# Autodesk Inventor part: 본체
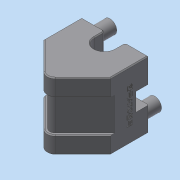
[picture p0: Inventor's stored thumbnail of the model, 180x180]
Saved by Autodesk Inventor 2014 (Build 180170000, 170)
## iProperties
Created: 2025-02
Part Number: 본체
Material: 일반
Document SubType Name: Modeling
Designer: dg
Density: 1 g/cm^3
Appearance: 기본값
Author: dg
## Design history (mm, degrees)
sketch "스케치1"
  geometry: L1 (-37, -21)-(0, -58); L2 (0, -58)-(37, -21); L3 (-37, -21)-(-37, 21); L4 (-37, 21)-(37, 21); L5 (37, 21)-(37, -21); 3 further points
  constraints: 10 end point, 2 horizontal alignment, 2 midpoint, 2 vertical alignment, 1 parallel, 1 perpendicular, 1 vertical
  dimensions: "d1" = 90 deg angle of L2 L1; "d2" = 42 distance of L4.end L2.end; "d3" = 74 distance of L3.end L4.end
extrude "돌출1" new body sketch "스케치1" stored distance "d4" = 74; taper "d5" = 0 deg
sketch "스케치2"
  geometry: L1 (37, 21)-(-37, 21) reference; L2 (-37, 21)-(-37, -21) reference; L3 (-11, 9)-(-11, 21); L4 (11, 9)-(11, 21); A1 r 11 centre (0, 9) between (-11, 9) and (11, 9); 1 further point
  constraints: 4 end point, 2 parallel, 2 point on circle, 2 point on line, 2 tangent, 1 centre point, 1 vertical alignment
  dimensions: "d6" = 12 distance from line of A1.centre L1; "d7" = 22 diameter of A1
extrude "돌출2" cut sketch "스케치2" stored distance "d8" = 74; taper "d9" = 0 deg
sketch "스케치3"
  geometry: L1 (48, 74)-(48, 0) reference; L2 (74, 0)-(48, 0) reference; L3 (74, 74)-(74, 0) reference; L4 (48, 74)-(74, 74) reference; C1 r 21 at (37, 37); 1 further point
  constraints: 1 centre point, 1 coincident
  dimensions: "d10" = 42 diameter of C1
extrude "돌출3" cut sketch "스케치3" distance "d11" = 8; taper "d12" = 0 deg
sketch "스케치4"
  geometry: C1 r 16 at (37, 37); A1 r 21 centre (37, 37) between (26, 54.889) and (26, 19.111) reference
  constraints: 1 centre point, 1 coincident
  dimensions: "d13" = 32 diameter of C1
extrude "돌출4" cut sketch "스케치4" distance "d14" = 20; taper "d15" = 0 deg
sketch "스케치5"
  geometry: L1 (16, -7)-(16, 13) reference; L2 (16, 13)-(21, 13) reference; L3 (21, 13)-(21, 21) reference; L4 (21, 21)-(37, 21) reference; L5 (37, 21)-(37, -21) reference; L6 (37, -21)-(0, -58) reference; L7 (0, -58)-(-37, -21) reference; L8 (-37, -21)-(-37, 21) reference; L9 (-37, 21)-(-21, 21) reference; L10 (-21, 21)-(-21, 13) reference; L11 (-21, 13)-(-16, 13) reference; L12 (-16, 13)-(-16, -7) reference; L13 (-16, -7)-(16, -7) reference; L14 (-23, 21)-(-37, 7); L15 (23, 21)-(37, 7); 1 further point
  constraints: 4 end point, 4 point on line, 2 perpendicular
  dimensions: "d16" = 14 distance of L14.start L8.end; "d17" = 14 distance of L4.end L15.start
extrude "돌출5" cut sketch "스케치5" stored distance "d18" = 20; taper "d19" = 0 deg
sketch "스케치6"
  geometry: L1 (19.799, 20)-(19.799, 0) reference; 4 further points
  constraints: 1 horizontal alignment, 1 midpoint, 1 vertical alignment
hole "구멍1" sketch "스케치6" at (9.899, 10) diameter "d20" = 8; stored, may be unused: countersink angle "d24" = 90 deg, drill point angle "d26" = 118 deg; dims "d21" = 6, "d22" = 13, "d23" = 3, "d25" = 8
sketch "스케치7"
  geometry: L1 (0, -58)-(-37, -21) reference; L2 (37, -21)-(0, -58) reference; L3 (34.879, -18.879)-(4.243, -49.515); L4 (-4.243, -49.515)-(-34.879, -18.879); L5 (-37, -21)-(-37, 21) reference; L6 (37, 21)-(37, -21) reference; L7 (-34.879, -18.879)-(-37, -16.757); L8 (34.879, -18.879)-(37, -16.757); A1 r 6 centre (0, -45.272) between (-4.243, -49.515) and (4.243, -49.515); 2 further points
  constraints: 8 end point, 4 point on line, 2 point on circle, 2 tangent, 1 centre point, 1 collinear, 1 horizontal alignment, 1 perpendicular, 1 vertical alignment, 1 other
  dimensions: "d27" = 3 distance between parallel lines of L1 L4; "d28" = 6 radius of A1; "d29" = 30.63604 horizontal distance of L4.start L4.end
extrude "돌출6" cut sketch "스케치7" stored distance "d30" = 36; taper "d31" = 0 deg
fillet "모깎기1" dims "d32" = 9
sketch "스케치8"
  geometry: L1 (14, 47)-(14, 27) reference; L2 (12.251, 12.251)-(37, 37); L3 (37, 37)-(26.927, 37); L4 (37, 37)-(61.749, 61.749); C1 r 7.5 at (12.251, 12.251); C2 r 7.5 at (61.749, 61.749); A1 r 21 centre (37, 37) between (26, 54.889) and (26, 19.111) reference; A2 r 35 centre (37, 37) between (12.251, 12.251) and (61.749, 61.749)
  constraints: 6 end point, 3 centre point, 2 point on circle, 1 coincident, 1 collinear, 1 equal radius, 1 perpendicular
  dimensions: "d33" = 70 diameter of A2; "d34" = 45 deg angle of L3 L2; "d35" = 15 diameter of C1; "d36" = 10.07267 distance of L2.end L3.end
extrude "돌출7" join sketch "스케치8" distance "d37" = 19; taper "d38" = 0 deg
sketch "스케치9"
  geometry: C1 r 7.5 at (0, 0) reference; C2 r 7.5 at (-49.497, -49.497) reference; 3 further points
  constraints: 2 coincident
hole "구멍2" sketch "스케치9" at (0, 0), (-49.497, -49.497) diameter "d39" = 4.917; stored, may be unused: countersink angle "d43" = 90 deg, drill point angle "d45" = 118 deg; dims "d40" = 12, "d41" = 13, "d42" = 3, "d44" = 14
sketch "스케치10"
  geometry: L1 (-4.751, 61)-(-19.751, 61) reference; 2 further points
  constraints: 1 coincident, 1 other
  dimensions: "d46" = 40 distance from line of point (-37, 21) L1
feature "엠보싱1" sketch "스케치10" dims "d47" = 0.5, "d48" = 0
chamfer "모따기1" distance "d49" = 1; stored, may be unused: second distance "d50" = 2, angle "d51" = 45 deg
chamfer "모따기2" distance "d52" = 1; stored, may be unused: second distance "d53" = 2, angle "d54" = 45 deg
chamfer "모따기3" distance "d55" = 1; stored, may be unused: second distance "d56" = 2, angle "d57" = 45 deg
chamfer "모따기5" distance "d61" = 1; stored, may be unused: second distance "d62" = 2, angle "d63" = 45 deg
fillet "모깎기2" dims "d64" = 3
chamfer "모따기6" distance "d65" = 1; stored, may be unused: second distance "d66" = 2, angle "d67" = 45 deg
fillet "모깎기3" dims "d68" = 3
node "솔리드1"
mirror "대칭1"
node "투영된 루프1"
node "투영된 루프2"
node "절단 모서리 투영1"
